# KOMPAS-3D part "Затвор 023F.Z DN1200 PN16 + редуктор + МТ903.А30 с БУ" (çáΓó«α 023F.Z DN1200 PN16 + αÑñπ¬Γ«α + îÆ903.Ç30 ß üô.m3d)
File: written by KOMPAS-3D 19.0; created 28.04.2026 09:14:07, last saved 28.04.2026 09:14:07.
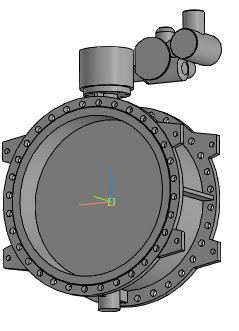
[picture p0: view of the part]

Document properties: Полное имя файла: ..\..\Затвор 023F.Z DN400-DN1600 + редуктор + МТ903\Затвор 023F.Z DN1200 PN16 + редуктор + МТ903.А30 с БУ.a3d

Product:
- Part/product: Затвор 023F.Z DN1200 PN16 + редуктор + МТ903.А30 с БУ
    Масса: 2494.98

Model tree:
1. Операция без истории:1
